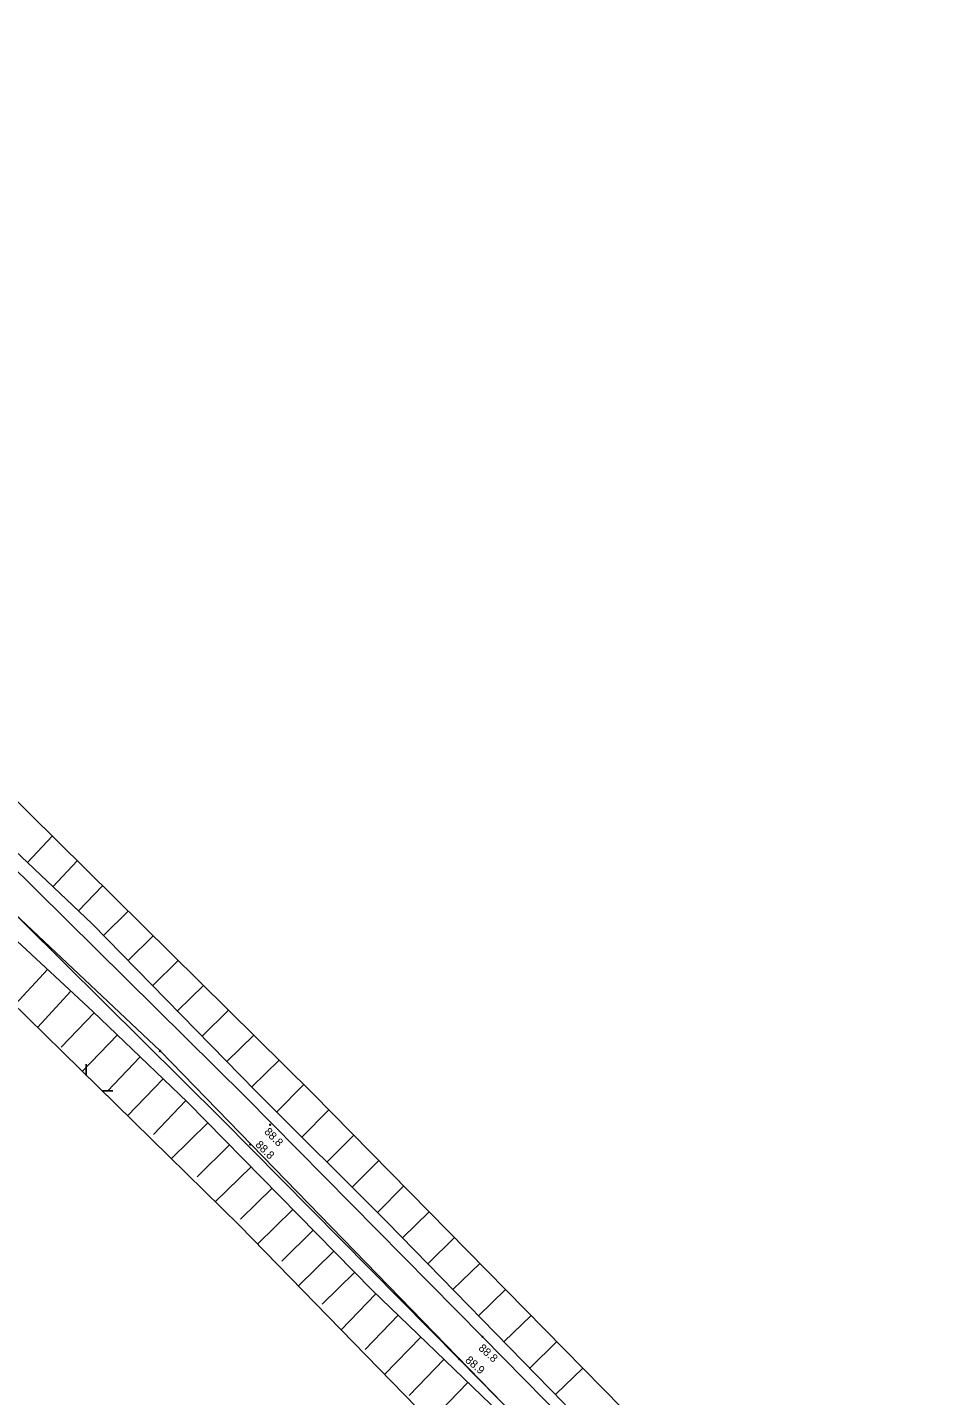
# Model space of a CAD drawing. Extents: x 7506075 to 7506993, y 5784375 to 5786367.
# Drawn here: x 7506194.5 to 7506280.8, y 5786221.4 to 5786349.7 of the extents above; entities that cross this region are included whole.
import ezdxf

# ---------------------------------------------------------------- set-up
doc = ezdxf.new("R2010")
doc.units = 0
for name, color, linetype in [('000 Inne (niezydentyfikowane)', 7, 'Continuous'), ('203-punkt graniczny', 7, 'Continuous'), ('216-obręb ewidencyjny', 7, 'Continuous'), ('218-kontur użytku gruntowego', 7, 'Continuous'), ('219-działka ewidencyjna', 7, 'Continuous'), ('jezdnia', 7, 'Continuous'), ('pikieta sztuczna', 7, 'Continuous'), ('pikieta sztuczna-Atr2', 7, 'Continuous'), ('wał przeciwpowodziowy', 7, 'Continuous'), ('Wstawianie ramki sekcyjnej z opisem', 7, 'Continuous')]:
    doc.layers.add(name, color=color, linetype=linetype)

# ---------------------------------------------------------------- blocks, each defined once
blk = doc.blocks.new('PW01')
blk.add_circle((0, 0), 0.045)
blk = doc.blocks.new('203')
blk.add_circle((0, 0), 0.045)

msp = doc.modelspace()

# ---------------------------------------------------------------- linework, layer by layer
at = {"layer": '000 Inne (niezydentyfikowane)'}
for p, q in [((7506194.48, 5786271.39), (7506196.813, 5786273.857)), ((7506196.87, 5786269.12), (7506199.159, 5786271.544)), ((7506199.27, 5786266.86), (7506201.508, 5786269.226)), ((7506201.61, 5786264.56), (7506203.931, 5786266.835)), ((7506203.92, 5786262.21), (7506206.276, 5786264.522)), ((7506196.37, 5786261.38), (7506193.33, 5786258.1)), ((7506206.22, 5786259.86), (7506208.622, 5786262.208)), ((7506208.54, 5786257.5), (7506210.977, 5786259.885)), ((7506198.56, 5786259.35), (7506195.413, 5786255.949)), ((7506200.75, 5786257.32), (7506197.65, 5786254.09)), ((7506210.85, 5786255.13), (7506213.335, 5786257.559)), ((7506202.91, 5786255.26), (7506199.619, 5786251.825)), ((7506213.18, 5786252.76), (7506215.699, 5786255.226)), ((7506205.06, 5786253.2), (7506201.99, 5786249.99)), ((7506215.5, 5786250.38), (7506218.067, 5786252.89)), ((7506207.2, 5786251.14), (7506203.864, 5786247.662)), ((7506217.85, 5786248.03), (7506220.403, 5786250.586)), ((7506209.33, 5786249.1), (7506206.29, 5786245.93)), ((7506220.2, 5786245.68), (7506222.747, 5786248.227)), ((7506211.39, 5786247.01), (7506207.963, 5786243.643)), ((7506222.56, 5786243.33), (7506225.082, 5786245.852)), ((7506213.43, 5786244.94), (7506210.38, 5786241.94)), ((7506224.92, 5786240.97), (7506227.418, 5786243.475)), ((7506215.44, 5786242.89), (7506212.085, 5786239.601)), ((7506217.41, 5786240.88), (7506214.45, 5786237.97)), ((7506227.28, 5786238.61), (7506229.761, 5786241.091)), ((7506219.36, 5786238.9), (7506216.045, 5786235.642)), ((7506229.64, 5786236.22), (7506232.144, 5786238.668)), ((7506221.28, 5786236.94), (7506218.34, 5786234.05)), ((7506232, 5786233.8), (7506234.513, 5786236.258)), ((7506223.2, 5786234.98), (7506219.873, 5786231.714)), ((7506225.15, 5786233), (7506222.11, 5786230.01)), ((7506234.37, 5786231.38), (7506236.888, 5786233.842)), ((7506227.14, 5786230.99), (7506223.881, 5786227.602)), ((7506236.76, 5786228.94), (7506239.282, 5786231.407)), ((7506229.22, 5786228.99), (7506226.13, 5786225.78)), ((7506239.15, 5786226.49), (7506241.685, 5786228.963)), ((7506231.35, 5786226.94), (7506227.958, 5786223.42)), ((7506241.56, 5786224.03), (7506244.097, 5786226.509)), ((7506233.52, 5786224.84), (7506230.27, 5786221.46)), ((7506243.98, 5786221.55), (7506246.528, 5786224.036)), ((7506235.76, 5786222.69), (7506232.237, 5786219.03))]:
    msp.add_line(p, q, dxfattribs=at)
at = {"layer": '216-obręb ewidencyjny'}
for points in [[(7506206.92, 5786253.74), (7506145.91, 5786311.21)], [(7506280.83, 5786177.75), (7506206.92, 5786253.74)]]:
    msp.add_lwpolyline(points, dxfattribs=at)
at = {"layer": '218-kontur użytku gruntowego'}
for points in [[(7506145.91, 5786311.21), (7506206.92, 5786253.74)], [(7506206.92, 5786253.74), (7506280.83, 5786177.75)]]:
    msp.add_lwpolyline(points, dxfattribs=at)
at = {"layer": '219-działka ewidencyjna'}
for points in [[(7506206.92, 5786253.74), (7506145.91, 5786311.21)], [(7506145.91, 5786311.21), (7506206.92, 5786253.74)], [(7506280.83, 5786177.75), (7506206.92, 5786253.74)], [(7506206.92, 5786253.74), (7506280.83, 5786177.75)]]:
    msp.add_lwpolyline(points, dxfattribs=at)
at = {"layer": 'jezdnia'}
for points in [[(7506192.56, 5786271.55), (7506214.92, 5786249.44), (7506237.15, 5786226.96), (7506260.58, 5786203.15)], [(7506258.34, 5786201.07), (7506234.96, 5786224.88), (7506212.75, 5786247.31), (7506190.42, 5786269.4)]]:
    msp.add_lwpolyline(points, dxfattribs=at)
at = {"layer": 'wał przeciwpowodziowy'}
for points in [[(7506140.73, 5786325.93), (7506189.34, 5786281.23), (7506221.23, 5786249.77), (7506250.23, 5786220.27), (7506273.28, 5786195.13), (7506271.06, 5786193.16), (7506255.61, 5786208.85), (7506244.73, 5786220.78), (7506228.2, 5786237.69), (7506215.87, 5786250.01), (7506200.56, 5786265.64), (7506184.79, 5786280.55), (7506165.11, 5786298.76), (7506150.05, 5786313.07), (7506133.89, 5786327.99), (7506114.29, 5786345.83), (7506110.66, 5786348.67), (7506111.31, 5786349.65)], [(7506140.73, 5786325.93), (7506189.34, 5786281.23), (7506221.23, 5786249.77), (7506250.23, 5786220.27), (7506273.28, 5786195.13), (7506271.06, 5786193.16), (7506255.61, 5786208.85), (7506244.73, 5786220.78), (7506228.2, 5786237.69), (7506215.87, 5786250.01), (7506200.56, 5786265.64), (7506184.79, 5786280.55), (7506165.11, 5786298.76), (7506150.05, 5786313.07), (7506133.89, 5786327.99), (7506114.29, 5786345.83), (7506110.66, 5786348.67), (7506111.31, 5786349.65)], [(7506109.56, 5786340.85), (7506127.14, 5786325.64), (7506146.91, 5786309.3), (7506156.33, 5786299.83), (7506169.02, 5786287.79), (7506186.4, 5786270.61), (7506200.62, 5786257.45), (7506209.49, 5786248.95), (7506226.78, 5786231.34), (7506243.05, 5786215.67), (7506258.34, 5786201.07), (7506261.09, 5786197.23), (7506267.45, 5786190.29), (7506263.46, 5786186.75), (7506261.87, 5786188.63), (7506214.35, 5786237.38), (7506176.25, 5786274.74), (7506108.37, 5786329.67), (7506103.95, 5786333.77), (7506095.98, 5786340.51), (7506101.05, 5786347.19)], [(7506109.56, 5786340.85), (7506127.14, 5786325.64), (7506146.91, 5786309.3), (7506156.33, 5786299.83), (7506169.02, 5786287.79), (7506186.4, 5786270.61), (7506200.62, 5786257.45), (7506209.49, 5786248.95), (7506226.78, 5786231.34), (7506243.05, 5786215.67), (7506258.34, 5786201.07), (7506261.09, 5786197.23), (7506267.45, 5786190.29), (7506263.46, 5786186.75), (7506261.87, 5786188.63), (7506214.35, 5786237.38), (7506176.25, 5786274.74), (7506108.37, 5786329.67), (7506103.95, 5786333.77), (7506095.98, 5786340.51), (7506101.05, 5786347.19)]]:
    msp.add_lwpolyline(points, close=True, dxfattribs=at)
at = {"layer": 'Wstawianie ramki sekcyjnej z opisem'}
for points in [[(7506200, 5786251.451), (7506200, 5786252.5)], [(7506201.48, 5786250), (7506202.5, 5786250)]]:
    msp.add_lwpolyline(points, dxfattribs=at)

# ---------------------------------------------------------------- block references
at = {"layer": '203-punkt graniczny'}
msp.add_blockref('203', (7506206.92, 5786253.74), dxfattribs=at)
at = {"layer": 'pikieta sztuczna'}
for p in [(7506217.23, 5786246.83), (7506215.36, 5786244.99), (7506237.15, 5786226.96), (7506234.96, 5786224.88)]:
    msp.add_blockref('PW01', p, dxfattribs=at)

# ---------------------------------------------------------------- texts
at = {"layer": 'pikieta sztuczna-Atr2'}
for s, rotation, p in [('88.8', 314.883, (7506216.625, 5786246.115)), ('88.8', 315.636, (7506215.796, 5786244.897)), ('88.8', 318.291, (7506236.702, 5786225.807)), ('88.9', 319.753, (7506235.457, 5786224.669))]:
    msp.add_text(s, height=0.75, rotation=rotation, dxfattribs=at).set_placement(p)

doc.saveas('drawing.dxf')
